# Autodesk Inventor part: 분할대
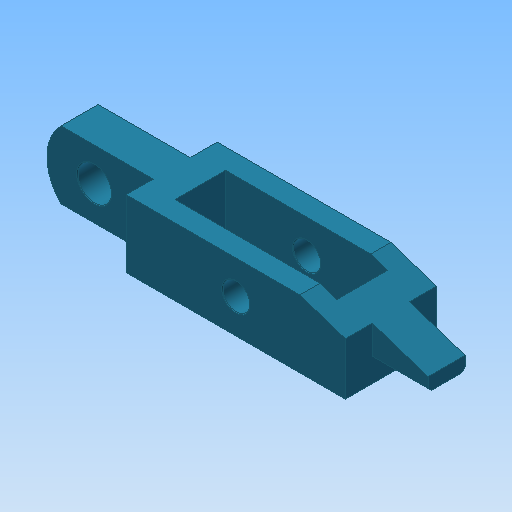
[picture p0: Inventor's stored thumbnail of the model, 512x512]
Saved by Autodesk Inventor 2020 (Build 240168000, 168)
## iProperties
Created: 2016-11
Part Number: 분할대
Material: 강철, 연강
Document SubType Name: Modeling
Designer: mduedu
Density: 7.86 g/cm^3
Appearance: 터키옥색
Mass: 206.904 g
Surface Area: 106.894 cm^2
Volume: 26.3237 cm^3
Author: mduedu
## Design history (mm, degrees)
sketch "스케치1"
  geometry: L1 (32.5, 13.5)-(-32.5, 13.5); L2 (-32.5, 13.5)-(-32.5, -13.5); L3 (-32.5, -13.5)-(32.5, -13.5); L4 (32.5, -13.5)-(32.5, 13.5); L5 (24, 7.5)-(-24, 7.5); L6 (-24, 7.5)-(-24, -7.5); L7 (-24, -7.5)-(24, -7.5); L8 (24, -7.5)-(24, 7.5); L9 (24, 0)-(-24, 0); L10 (0, -13.5)-(0, 13.5); 4 further points
  constraints: 20 end point, 7 midpoint, 4 parallel, 2 coincident, 2 horizontal, 2 perpendicular, 1 horizontal alignment
  dimensions: "d0" = 15 distance of L5.end L6.end; "d2" = 27 distance between parallel lines of L1 L3; "d3" = 48 distance of L5.start L5.end; "d4" = 65 distance of L1.start L1.end
extrude "돌출1" new body sketch "스케치1" distance "d5" = 20; taper "d6" = 0 deg
sketch "스케치2"
  geometry: L1 (0, 0)-(65, 0) reference; L2 (65, 0)-(65, 20) reference; L3 (0, 20)-(65, 20) reference; L4 (0, 0)-(0, 20) reference; L5 (32.5, 0)-(32.5, 20); C1 r 4 at (32.5, 10)
  constraints: 2 end point, 2 midpoint, 1 centre point
  dimensions: "d7" = 8 diameter of C1
extrude "돌출2" cut sketch "스케치2" extent not by distance; stored distance "d8" = 20; taper "d9" = 0 deg
chamfer "모따기1" distance "d10" = 0.2; stored, may be unused: second distance "d11" = 2, angle "d12" = 45 deg
sketch "스케치3"
  geometry: L1 (-32.5, 0)-(-32.5, 20) reference; L2 (-32.5, 20)-(-59.798, 20); L3 (-64, 20)-(-64, 0); L4 (-64, 0)-(-59.798, 0); L5 (-32.5, 0)-(-32.5, 20); L6 (-59.798, 20)-(-64, 20); L7 (-59.798, 0)-(-32.5, 0); C1 r 4.2 at (0, 10) reference; C2 r 5 at (-50, 10); A1 r 14 centre (-50, 10) between (-59.798, 20) and (-59.798, 0); 1 further point
  constraints: 12 end point, 5 parallel, 2 centre point, 2 horizontal, 2 perpendicular, 2 point on circle, 1 coincident, 1 horizontal alignment, 1 tangent
  dimensions: "d13" = 64 distance from line of L3 C1.centre; "d14" = 14 radius of A1; "d15" = 10 diameter of C2
extrude "돌출3" join sketch "스케치3" stored distance "d16" = 11; taper "d17" = 0 deg
sketch "스케치4"
  geometry: L1 (32.5, 0)-(32.5, 20) reference; L2 (32.5, 20)-(49, 20); L3 (49, 20)-(49, 6); L4 (49, 6)-(32.5, 6); L5 (32.5, 6)-(32.5, 20); L6 (32.5, 0)-(-32.5, 0) reference; 1 further point
  constraints: 8 end point, 2 parallel, 1 horizontal, 1 perpendicular
  dimensions: "d18" = 16.5 distance of L1.end L2.end; "d19" = 6 distance between parallel lines of L4 L6
extrude "돌출4" join sketch "스케치4" stored distance "d20" = 11; taper "d21" = 0 deg
chamfer "모따기2" distance "d22" = 30; stored, may be unused: second distance "d23" = 10, angle "d24" = 45 deg
chamfer "모따기3" distance "d25" = 1; stored, may be unused: second distance "d26" = 10, angle "d27" = 45 deg
chamfer "모따기4" distance "d28" = 0.2; stored, may be unused: second distance "d29" = 10, angle "d30" = 45 deg
node "솔리드1"
node "투영된 루프1"
